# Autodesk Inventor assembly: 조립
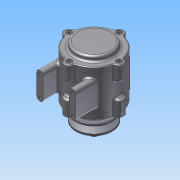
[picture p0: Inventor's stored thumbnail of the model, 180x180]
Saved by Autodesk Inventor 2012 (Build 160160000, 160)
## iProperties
Created: 2015-03
Part Number: 조립
Document SubType Name: Assembly
Designer: net
Author: net
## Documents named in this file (11)
- C:\Users\net\Desktop\450305V1046\조립.iam
- C:\Users\net\Desktop\450305V1046\본체.ipt
- C:\Users\net\Desktop\450305V1046\커버.ipt
- C:\Users\net\Desktop\450305V1046\커버2.ipt
- C:\Users\net\Desktop\450305V1046\축.ipt
- C:\Users\net\Desktop\450305V1046\베어링 6204.ipt
- C:\Users\net\Desktop\450305V1046\오일실.ipt
- C:\Users\net\Desktop\450305V1046\키(4 x 4 x 12).ipt
- C:\Users\net\Desktop\450305V1046\V벨트풀리.ipt
- C:\Users\net\Desktop\450305V1046\너트 M12x1.25.ipt
- C:\Users\net\Desktop\450305V1046\M 4 x 12.ipt
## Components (14 placed, 6 different names)
1. KS B 2023 6204 - 20 x 47 x 14:1
2. KS B 2023 6204 - 20 x 47 x 14:2
3. KS B 2804 D D - 20 32 8:1
4. KS B 1311 (I) 4 x 4 x 12:1 — 각도:1
5. 그루브 풀리1:1
6. KS B 1012 클래스 1 일반 - 미터 M12x1.25:1
7. KS B 1003 - 미터 M 4 x 12:2
8. KS B 1003 - 미터 M 4 x 12:3
9. KS B 1003 - 미터 M 4 x 12:4
10. KS B 1003 - 미터 M 4 x 12:5
11. KS B 1003 - 미터 M 4 x 12:1
12. KS B 1003 - 미터 M 4 x 12:6
13. KS B 1003 - 미터 M 4 x 12:7
14. KS B 1003 - 미터 M 4 x 12:8
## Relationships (1: Angle 1)
- 각도:1 [Angle]: KS B 1311 (I) 4 x 4 x 12:1
